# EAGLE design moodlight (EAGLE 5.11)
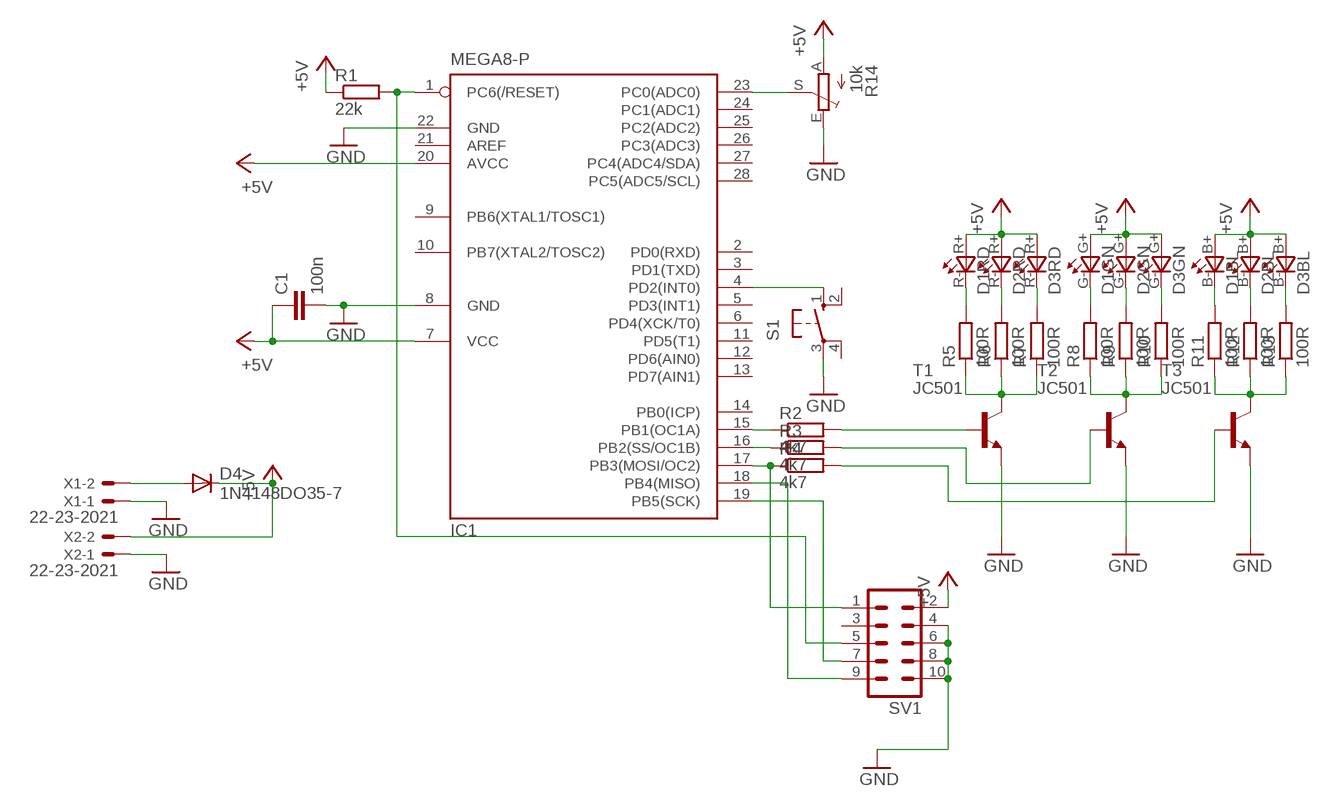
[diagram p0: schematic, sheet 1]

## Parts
C1  100n  C-EUC0805  [C0805]
D1  RGB-SUPERFLUX-LED  [ULTRAFLUX-RGB-LED-6]
D2  RGB-SUPERFLUX-LED  [ULTRAFLUX-RGB-LED-6]
D3  RGB-SUPERFLUX-LED  [ULTRAFLUX-RGB-LED-6]
D4  1N4148DO35-7  [DO35-7]
IC1  MEGA8-P  [DIL28-3]
R1  22k  R-EU_0204/2V  [0204V]
R2  4k7  R-EU_0204/2V  [0204V]
R3  4k7  R-EU_0204/2V  [0204V]
R4  4k7  R-EU_0204/2V  [0204V]
R5  100R  R-EU_0207/7  [0207/7]
R6  100R  R-EU_0207/7  [0207/7]
R7  100R  R-EU_0207/7  [0207/7]
R8  100R  R-EU_0207/7  [0207/7]
R9  100R  R-EU_0207/7  [0207/7]
R10  100R  R-EU_0207/7  [0207/7]
R11  100R  R-EU_0207/7  [0207/7]
R12  100R  R-EU_0207/7  [0207/7]
R13  100R  R-EU_0207/7  [0207/7]
R14  10k  TRIM_EU-CA9V  [CA9V]
S1  10-XX  [B3F-10XX]
SV1  ML10  [ML10]
T1  JC501  -NPN-TO92-ECB  [TO92-ECB]
T2  JC501  -NPN-TO92-ECB  [TO92-ECB]
T3  JC501  -NPN-TO92-ECB  [TO92-ECB]
X1  22-23-2021  [22-23-2021]
X2  22-23-2021  [22-23-2021]

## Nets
+5V: C1.1 D1.B+(BL:A) D1.G+(GN:A) D1.R+(RD:A) D2.B+(BL:A) D2.G+(GN:A) D2.R+(RD:A) D3.B+(BL:A) D3.G+(GN:A) D3.R+(RD:A) D4.C IC1.7(VCC) IC1.20(AVCC) R1.1 R14.A SV1.2 X2.2
GND: C1.2 IC1.8(GND) IC1.22(GND) R14.E S1.3(P) SV1.4 SV1.6 SV1.8 SV1.10 T1.E T2.E T3.E X1.1 X2.1
N$1: R2.2 T1.B
N$2: R3.2 T2.B
N$3: R4.2 T3.B
N$4: IC1.15(PB1(OC1A)) R2.1
N$5: IC1.16(PB2(SS/OC1B)) R3.1
N$6: IC1.17(PB3(MOSI/OC2)) R4.1 SV1.1
N$7: IC1.1(PC6(/RESET)) R1.2 SV1.5
N$8: R5.1 R6.1 R7.1 T1.C
N$9: R8.1 R9.1 R10.1 T2.C
N$10: R11.1 R12.1 R13.1 T3.C
N$11: D3.B-(BL:C) R13.2
N$12: D2.B-(BL:C) R12.2
N$13: D1.B-(BL:C) R11.2
N$14: D3.G-(GN:C) R10.2
N$15: D2.G-(GN:C) R9.2
N$16: D1.G-(GN:C) R8.2
N$17: D3.R-(RD:C) R7.2
N$18: D2.R-(RD:C) R6.2
N$19: D1.R-(RD:C) R5.2
N$20: IC1.23(PC0(ADC0)) R14.S
N$21: IC1.4(PD2(INT0)) S1.1(S)
N$22: D4.A X1.2
N$23: IC1.19(PB5(SCK)) SV1.7
N$24: IC1.18(PB4(MISO)) SV1.9
Unconnected: IC1.2(PD0(RXD)) IC1.3(PD1(TXD)) IC1.5(PD3(INT1)) IC1.6(PD4(XCK/T0)) IC1.9(PB6(XTAL1/TOSC1)) IC1.10(PB7(XTAL2/TOSC2)) IC1.11(PD5(T1)) IC1.12(PD6(AIN0)) IC1.13(PD7(AIN1)) IC1.14(PB0(ICP)) IC1.21(AREF) IC1.24(PC1(ADC1)) IC1.25(PC2(ADC2)) IC1.26(PC3(ADC3)) IC1.27(PC4(ADC4/SDA)) IC1.28(PC5(ADC5/SCL)) S1.2(S1) S1.4(P1) SV1.3

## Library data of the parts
C1 = rcl:C-EU: CAPACITOR, European symbol
D1-D3 = eigene:RGB-SUPERFLUX-LED: RGB Superflux LED, 6 Pins, RM 2,54 "Piranha", diffus
D4 = diode:1N4148: DIODE
IC1 = atmel:MEGA8-P: MICROCONTROLLER 8 Kbytes FLASH, 1 kbytes SRAM, 512 bytes EEPROM, USART, 4-channel 10 bit ADC, 2-channel 8 bit ADC Pin compatible with Atmega48, ATMega88, ATMega168 Source: avr.lbr; OC_FARNELL: unknown; OC_NEWARK: unknown
R1-R13 = resistor:R-EU_: RESISTOR, European symbol
R14 = pot:TRIM_EU-: POTENTIOMETER
S1 = switch-omron:10-XX: OMRON SWITCH; MPN: B3F-1000; OC_FARNELL: 176432; OC_NEWARK: 36M3542
SV1 = con-harting-ml:ML10: HARTING; OC_FARNELL: unknown; OC_NEWARK: unknown
T1-T3 = transistor:*-NPN-: NPN Transistror BF959 corrected 2008.03.06
X1 X2 = con-molex:22-23-2021: .100" (2.54mm) Center Header - 2 Pin; MF: MOLEX; MPN: 22-23-2021; OC_FARNELL: 1462926; OC_NEWARK: 25C3832

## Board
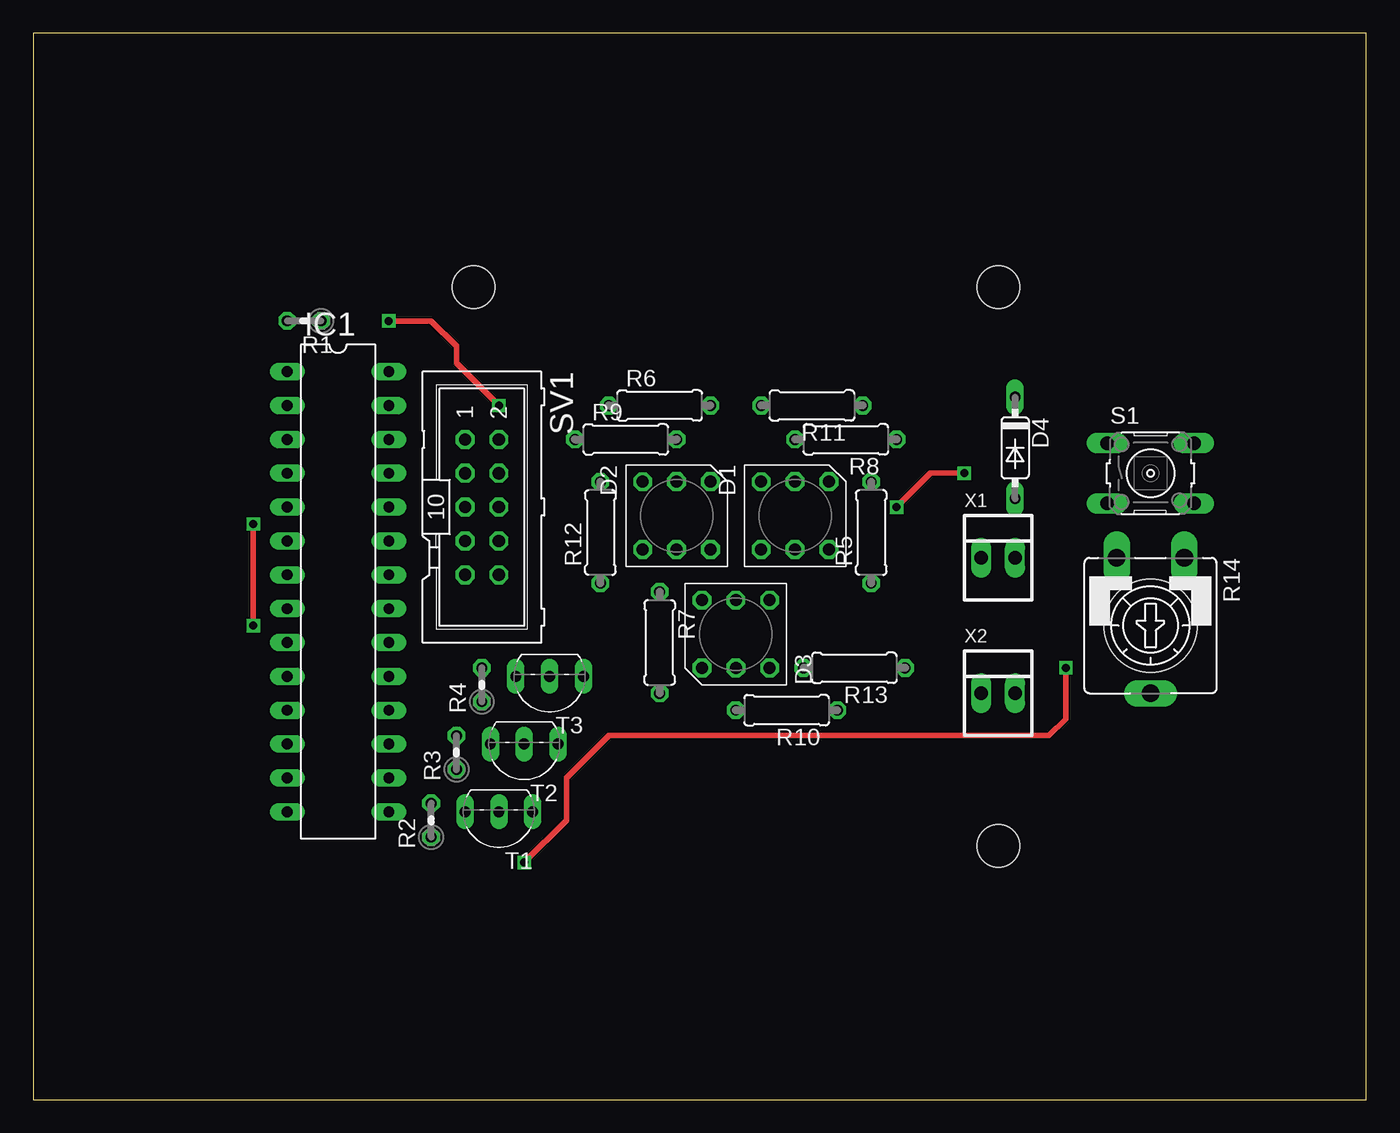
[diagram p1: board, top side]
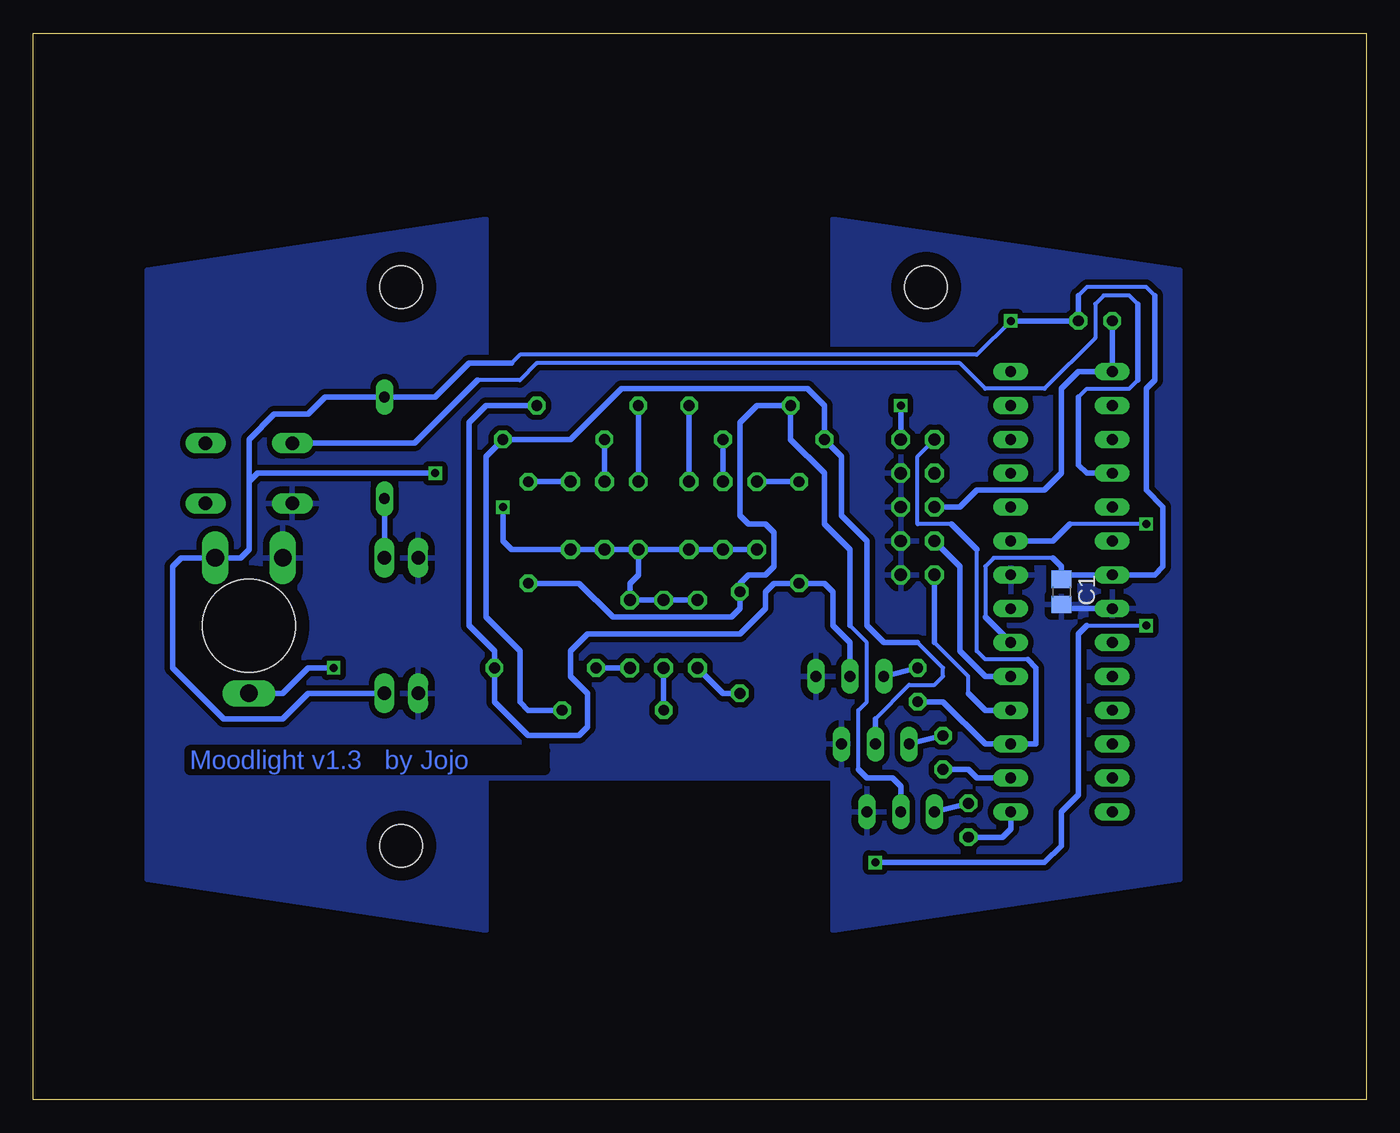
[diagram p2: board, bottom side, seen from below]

Size 100 x 80 mm. Coordinates in mm from the lower left corner, seen from the top.
Outline: 0,0 100,0 100,80 0,80 0,0
Copper layers (1*16): Top 0.035mm / dielectric 1.5mm / Bottom 0.035mm
Design rules "eigene": minimum track width 10mil, minimum drill 24mil, track to track 16mil, track to pad 20mil, pad to pad 16mil, via to via 16mil, smd to smd 16mil, copper to edge 40mil, drill to drill 8mil, minimum pad ring 10mil, minimum via ring 8mil, stop-mask expansion 4mil, vias tented up to drill 0mil, thermal gap 20mil
Holes 7 mm at 83.82,35.56
Holes 3.2 mm at 33.02,60.96 72.39,60.96 72.39,19.05

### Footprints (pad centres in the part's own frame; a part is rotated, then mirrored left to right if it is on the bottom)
C0805 = smd 1.3 x 1.5: 1 -0.95,0; 2 0.95,0
ULTRAFLUX-RGB-LED-6 = drill 0.9 octagon: B+ 2.54,-2.54; B- -2.54,-2.54; G+ 2.54,0; R+ 2.54,2.54 | drill 0.9 pad 1.422 octagon: G- -2.54,0; R- -2.54,2.54
DO35-7 = drill 0.813 long: A 3.81,0; C -3.81,0
DIL28-3 = drill 0.813 long: 1 -16.51,-3.81; 2 -13.97,-3.81; 3 -11.43,-3.81; 4 -8.89,-3.81; 5 -6.35,-3.81; 6 -3.81,-3.81; 7 -1.27,-3.81; 8 1.27,-3.81; 9 3.81,-3.81; 10 6.35,-3.81; 11 8.89,-3.81; 12 11.43,-3.81; 13 13.97,-3.81; 14 16.51,-3.81; 15 16.51,3.81; 16 13.97,3.81; 17 11.43,3.81; 18 8.89,3.81; 19 6.35,3.81; 20 3.81,3.81; 21 1.27,3.81; 22 -1.27,3.81; 23 -3.81,3.81; 24 -6.35,3.81; 25 -8.89,3.81; 26 -11.43,3.81; 27 -13.97,3.81; 28 -16.51,3.81
0204V = drill 0.813 octagon: 1 -1.27,0; 2 1.27,0
0207/7 = drill 0.813 octagon: 1 -3.81,0; 2 3.81,0
CA9V = drill 1.321 long: A -2.54,-5.08; E 2.54,-5.08; S 0,5.08
B3F-10XX = drill 1.016 long: 1 -3.251,2.261; 2 3.251,2.261; 3 -3.251,-2.261; 4 3.251,-2.261
ML10 = drill 0.914 octagon: 1 -5.08,-1.27; 2 -5.08,1.27; 3 -2.54,-1.27; 4 -2.54,1.27; 5 0,-1.27; 6 0,1.27; 7 2.54,-1.27; 8 2.54,1.27; 9 5.08,-1.27; 10 5.08,1.27
TO92-ECB = drill 0.813 long: B 2.54,0; C 0,0; E -2.54,0
22-23-2021 = drill 1 long: 1 -1.27,0; 2 1.27,0

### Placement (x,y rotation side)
C1  22.86,38.1 270 bottom
D1  57.15,43.81 270 top
D2  48.26,43.81 270 top
D3  52.7,34.92 90 top
D4  73.66,48.9 270 top
IC1  22.86,38.1 270 top
R1  20.32,58.42 180 top
R2  29.84,20.95 90 top
R3  31.75,26.04 90 top
R4  33.66,31.11 90 top
R5  62.87,42.55 90 top
R6  46.99,52.07 0 top
R7  46.99,34.29 270 top
R8  60.96,49.53 180 top
R9  44.45,49.53 0 top
R10  56.52,29.21 180 top
R11  58.42,52.07 180 top
R12  42.55,42.55 90 top
R13  61.59,32.38 180 top
R14  83.82,35.56 180 top
S1  83.82,46.99 0 top
SV1  33.66,44.45 270 top
T1  34.92,21.59 180 top
T2  36.83,26.67 180 top
T3  38.73,31.75 180 top
X1  72.39,40.64 0 top
X2  72.39,30.48 0 top

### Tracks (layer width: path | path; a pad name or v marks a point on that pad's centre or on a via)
+5V  (via drill 0.6)
  Top 0.406: v26.67,58.42 29.84,58.42 31.75,56.52 31.75,55.24 v34.92,52.07 | v64.77,44.45 67.31,46.99 v69.85,46.99
  Bottom 0.305: 64.14,55.24 63.5,55.88 29.21,55.88 v26.67,58.42 | 15.88,60.33 16.51,60.96 20.95,60.96 21.59,60.33 | 23.5,40.64 27.94,40.64 28.57,40.01 28.57,36.2 | v34.92,52.07 34.92,50.16
  Bottom 0.406: D2.B+ D2.G+ D2.R+ D1.B+ | D1.B+ D1.G+ D1.R+ 64.14,41.27 64.77,41.91 v64.77,44.45 | D1.B+ 54.61,39.37 55.24,38.73 D3.B+ D3.G+ D3.R+ | 64.14,55.24 67.31,55.24 69.85,52.7 D4.C 78.11,52.7 79.38,51.44 81.92,51.44 83.82,49.53 83.82,46.35 | v26.67,58.42 R1.1 21.59,60.33 | X2.2 79.38,30.48 81.28,28.57 85.72,28.57 89.53,32.38 89.53,40.01 88.9,40.64 R14.A 84.45,40.64 83.82,41.27 83.82,46.35 | 15.88,60.33 15.88,53.98 16.51,53.34 16.51,45.72 15.24,44.45 15.24,40.01 15.88,39.37 IC1.7 22.86,39.37 C1.1 22.86,40.01 23.5,40.64 | 28.57,36.2 IC1.20 | 83.82,46.35 83.19,46.99 v69.85,46.99 | v34.92,52.07 SV1.2
GND
  Bottom 0.406: IC1.8 22.86,36.83 C1.2 | IC1.22 26.04,39.37
  pour Bottom: 13.97,16.51 40.01,12.7 40.01,24.13 66.04,24.13 66.04,12.7 91.44,16.51 91.44,62.23 66.04,66.04 66.04,55.88 40.01,55.88 40.01,66.04 13.97,62.23
N$1
  Bottom 0.406: R2.2 T1.B
N$2
  Bottom 0.406: R3.2 T2.B
N$3
  Bottom 0.406: R4.2 T3.B
N$4
  Bottom 0.406: IC1.15 26.67,20.32 27.3,19.68 R2.1
N$5
  Bottom 0.406: IC1.16 29.21,24.13 29.84,24.77 R3.1
N$6
  Bottom 0.305: SV1.1 33.66,48.26 33.66,43.18 31.11,43.18 | 29.21,41.27 29.21,33.66 28.57,33.02 25.4,33.02
  Bottom 0.406: R4.1 31.75,29.84 28.57,26.67 IC1.17 24.77,26.67 24.77,32.38 25.4,33.02 | 29.21,41.27 31.11,43.18
N$7
  Bottom 0.406: R1.2 IC1.1 21.59,54.61 22.86,53.34 22.86,46.99 24.13,45.72 29.21,45.72 30.48,44.45 SV1.5
N$8
  Bottom 0.305: 38.1,24.77 38.1,29.21 37.47,29.84 37.47,34.29 38.73,35.56
  Bottom 0.406: R5.1 59.05,38.73 56.52,36.2 47.62,36.2 46.99,36.83 R7.1 46.99,38.73 46.35,39.37 45.09,39.37 44.45,40.01 44.45,42.55 45.09,43.18 46.35,43.18 46.99,43.81 46.99,50.8 45.72,52.07 R6.1 43.18,49.53 40.64,46.99 40.64,43.18 38.73,41.27 38.73,35.56 | T1.C 34.92,23.5 35.56,24.13 37.47,24.13 38.1,24.77
N$9
  Bottom 0.305: 36.83,28.57 34.29,31.11 32.38,31.11 31.75,31.75 31.75,32.38 33.66,34.29
  Bottom 0.406: R10.1 62.87,29.21 63.5,29.84 63.5,33.66 66.04,36.2 66.04,48.26 R8.1 59.69,49.53 55.88,53.34 41.91,53.34 40.64,52.07 R9.1 39.37,48.26 39.37,43.81 37.47,41.91 37.47,35.56 36.2,34.29 33.66,34.29 | T2.C 36.83,28.57
N$10
  Bottom 0.406: R11.1 66.04,52.07 67.31,50.8 67.31,35.56 65.41,33.66 R13.1 65.41,29.84 62.87,27.3 59.05,27.3 58.42,27.94 58.42,30.48 59.69,31.75 59.69,33.66 58.42,34.92 46.99,34.92 45.09,36.83 45.09,38.1 44.45,38.73 R12.1 40.64,38.73 40.01,38.1 40.01,35.56 38.73,34.29 T3.C
N$11
  Bottom 0.406: D3.B- R13.2
N$12
  Bottom 0.406: R12.2 D2.B-
N$13
  Bottom 0.406: D1.B- R11.2
N$14
  Bottom 0.406: R10.2 D3.G-
N$15
  Bottom 0.406: D2.G- R9.2
N$16
  Bottom 0.406: D1.G- R8.2
N$17
  Bottom 0.406: R7.2 48.26,30.48 D3.R-
N$18
  Bottom 0.406: D2.R- R6.2
N$19
  Bottom 0.406: D1.R- R5.2
N$20  (via drill 0.6)
  Top 0.406: v16.51,35.56 v16.51,43.18 | v36.83,17.78 40.01,20.95 40.01,24.13 43.18,27.3 76.2,27.3 77.47,28.57 v77.47,32.38
  Bottom 0.305: v16.51,43.18 22.23,43.18 | 20.95,35.56 v16.51,35.56
  Bottom 0.406: IC1.23 23.5,41.91 22.23,43.18 | v36.83,17.78 24.13,17.78 22.86,19.05 22.86,21.59 21.59,22.86 21.59,34.92 20.95,35.56 | v77.47,32.38 79.38,32.38 81.28,30.48 R14.S
N$21
  Bottom 0.305: 66.67,53.98 63.5,53.98 62.23,55.24 30.48,55.24 28.57,53.34 24.13,53.34 20.32,57.15 20.32,59.69 19.68,60.33 17.78,60.33 17.14,59.69 | 17.14,53.98 17.78,53.34 20.95,53.34 21.59,52.7
  Bottom 0.406: S1.1 71.4,49.25 66.67,53.98 | 17.14,53.98 17.14,59.69 | 21.59,52.7 21.59,47.62 20.95,46.99 IC1.4
N$22
  Bottom 0.406: X1.2 D4.A
N$23
  Bottom 0.406: IC1.19 28.57,31.75 30.48,33.66 30.48,40.01 SV1.7
N$24
  Bottom 0.305: 29.84,30.48 29.84,31.75 32.38,34.29
  Bottom 0.406: IC1.18 28.57,29.21 29.84,30.48 | 32.38,34.29 SV1.9
N$25  (via drill 0.6)
  other vias: 83.82,35.56
N$26  (via drill 0.6)
  other vias: 33.02,60.96
N$27  (via drill 0.6)
  other vias: 72.39,60.96
N$28  (via drill 0.6)
  other vias: 72.39,19.05

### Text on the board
Bottom: Moodlight v1.3 by Jojo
